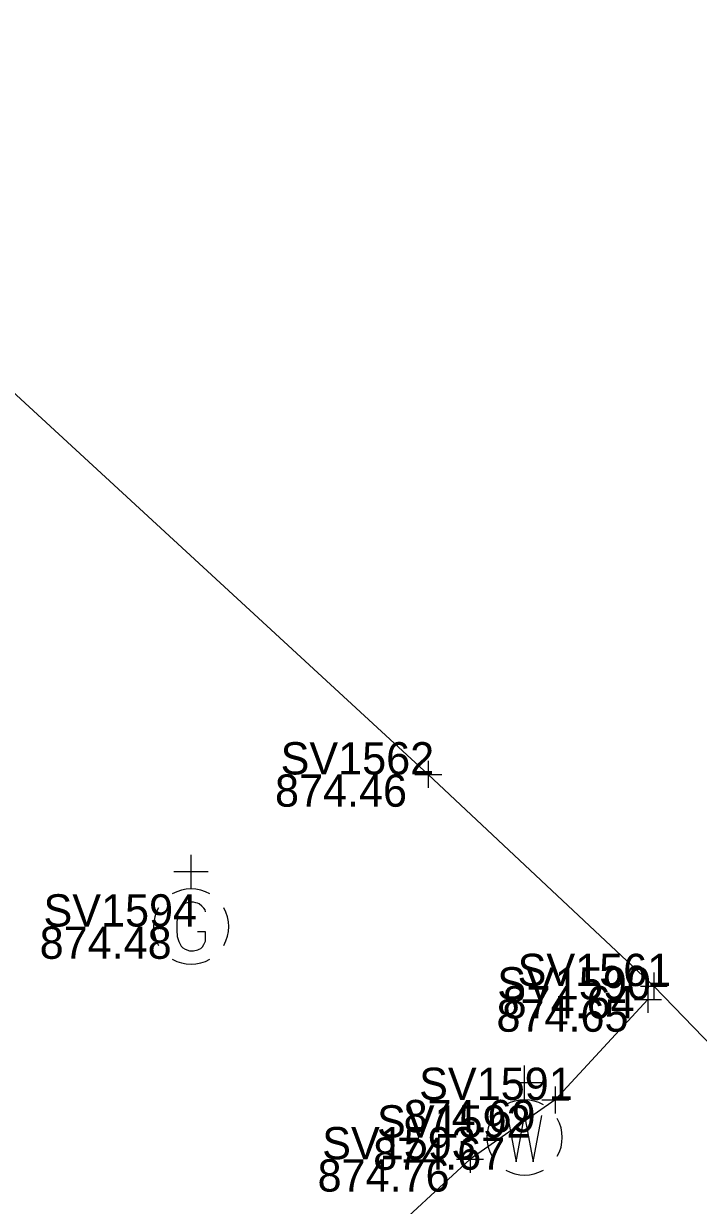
# Model space of a CAD drawing. Extents: x 1480001 to 1480402, y 379235 to 379603.
# Drawn here: x 1480145.99 to 1480171.08, y 379390.17 to 379434.1 of the extents above; entities that cross this region are included whole.
import ezdxf

# ---------------------------------------------------------------- set-up
doc = ezdxf.new("R2010")
doc.units = 0
for name, color, linetype in [('SV_X_Shot_Marker', 7, 'Continuous'), ('SV_X_Text_Elevation', 7, 'Continuous'), ('SV_X_Text_Name', 7, 'Continuous'), ('UT_X_Gas_Cells', 7, 'Continuous'), ('UT_X_Water', 7, 'Continuous'), ('UT_X_Water_Cells', 7, 'Continuous')]:
    doc.layers.add(name, color=color, linetype=linetype)

msp = doc.modelspace()

# ---------------------------------------------------------------- linework, layer by layer
at = {"layer": 'SV_X_Shot_Marker'}
for p, q in [((1480161.035, 379406.689), (1480161.035, 379405.689)), ((1480160.535, 379406.189), (1480161.535, 379406.189)), ((1480161.035, 379406.189), (1480161.035, 379406.189)), ((1480169.423, 379398.821), (1480169.423, 379397.821)), ((1480168.923, 379398.321), (1480169.923, 379398.321)), ((1480169.204, 379398.323), (1480169.204, 379397.323)), ((1480169.423, 379398.321), (1480169.423, 379398.321)), ((1480168.704, 379397.823), (1480169.704, 379397.823)), ((1480169.204, 379397.823), (1480169.204, 379397.823)), ((1480165.761, 379394.587), (1480165.761, 379393.587)), ((1480165.261, 379394.087), (1480166.261, 379394.087)), ((1480165.761, 379394.087), (1480165.761, 379394.087)), ((1480162.59, 379392.38), (1480162.59, 379391.38)), ((1480162.09, 379391.88), (1480163.09, 379391.88)), ((1480162.59, 379391.88), (1480162.59, 379391.88))]:
    msp.add_line(p, q, dxfattribs=at)
at = {"layer": 'UT_X_Gas_Cells'}
for p, q in [((1480152.218, 379401.934), (1480152.218, 379403.204)), ((1480152.855, 379402.569), (1480151.581, 379402.569)), ((1480152.218, 379400.534), (1480152.218, 379400.534))]:
    msp.add_line(p, q, dxfattribs=at)
msp.add_lwpolyline([(1480152.751, 379401.08), (1480152.737, 379401.151), (1480152.694, 379401.221), (1480152.623, 379401.292), (1480152.524, 379401.377), (1480152.453, 379401.406), (1480152.396, 379401.42), (1480152.311, 379401.434), (1480152.141, 379401.434), (1480152.071, 379401.42), (1480152.028, 379401.406), (1480151.971, 379401.377), (1480151.858, 379401.292), (1480151.787, 379401.193), (1480151.744, 379401.08), (1480151.716, 379400.924), (1480151.688, 379400.697), (1480151.688, 379400.399), (1480151.702, 379400.158), (1480151.759, 379399.974), (1480151.844, 379399.804), (1480151.915, 379399.747), (1480152, 379399.691), (1480152.156, 379399.634), (1480152.311, 379399.634), (1480152.467, 379399.662), (1480152.524, 379399.691), (1480152.581, 379399.719), (1480152.637, 379399.776), (1480152.694, 379399.861), (1480152.751, 379399.988), (1480152.751, 379400.343), (1480152.453, 379400.343)], dxfattribs=at)
for start, end in [(60.0184, 120.0157), (150.0184, 209.9816), (330.0184, 29.9816), (239.9843, 299.9816)]:
    msp.add_arc((1480152.218, 379400.534), 1.4, start, end, dxfattribs=at)
at = {"layer": 'UT_X_Water'}
for points in [[(1480225.088, 379345.601), (1480208.322, 379361.342), (1480207.346, 379362.25), (1480199.528, 379369.768), (1480193.21, 379375.651), (1480182.823, 379385.139), (1480177.927, 379389.525), (1480169.423, 379398.321), (1480161.035, 379406.189), (1480144.924, 379421.019), (1480134.739, 379430.559), (1480121.485, 379441.998), (1480113.085, 379450.369), (1480106.418, 379456.915), (1480094.539, 379467.985), (1480089.15, 379472.551), (1480086.751, 379474.713), (1480073.459, 379487.337), (1480068.123, 379493.187), (1480050.678, 379510.207), (1480044.404, 379515.873)], [(1480169.204, 379397.823), (1480165.761, 379394.087), (1480162.59, 379391.88), (1480159.156, 379388.706), (1480148.911, 379378.819), (1480120.344, 379350.087), (1480106.297, 379335.736), (1480080.736, 379308.289), (1480073.091, 379299.637), (1480056.748, 379281.628), (1480051.266, 379275.974)]]:
    msp.add_lwpolyline(points, dxfattribs=at)
at = {"layer": 'UT_X_Water_Cells'}
for p, q in [((1480164.62, 379394.09), (1480164.62, 379395.362)), ((1480165.255, 379394.727), (1480163.983, 379394.727)), ((1480164.62, 379392.69), (1480164.62, 379392.69))]:
    msp.add_line(p, q, dxfattribs=at)
msp.add_lwpolyline([(1480163.983, 379393.51), (1480164.302, 379391.787), (1480164.62, 379393.51), (1480164.94, 379391.787), (1480165.257, 379393.51)], dxfattribs=at)
for start, end in [(60.0184, 120.0157), (150.0184, 209.9816), (330.0184, 29.9816), (239.9843, 299.9816)]:
    msp.add_arc((1480164.62, 379392.692), 1.4, start, end, dxfattribs=at)

# ---------------------------------------------------------------- texts
at = {"layer": 'SV_X_Text_Elevation'}
for s, p in [('874.46', (1480155.338, 379404.989)), ('874.48', (1480146.587, 379399.334)), ('874.64', (1480163.801, 379397.121)), ('874.65', (1480163.573, 379396.623)), ('874.69', (1480160.12, 379392.887)), ('874.67', (1480158.989, 379391.49)), ('874.76', (1480156.921, 379390.68))]:
    msp.add_text(s, height=1.2, dxfattribs=at).set_placement(p)
at = {"layer": 'SV_X_Text_Name'}
for s, p in [('SV1562', (1480155.546, 379406.189)), ('SV1594', (1480146.729, 379400.534)), ('SV1561', (1480164.359, 379398.321)), ('SV1590', (1480163.602, 379397.823)), ('SV1591', (1480160.697, 379394.087)), ('SV1592', (1480159.131, 379392.69)), ('SV1593', (1480157.092, 379391.88))]:
    msp.add_text(s, height=1.2, dxfattribs=at).set_placement(p)

doc.saveas('drawing.dxf')
